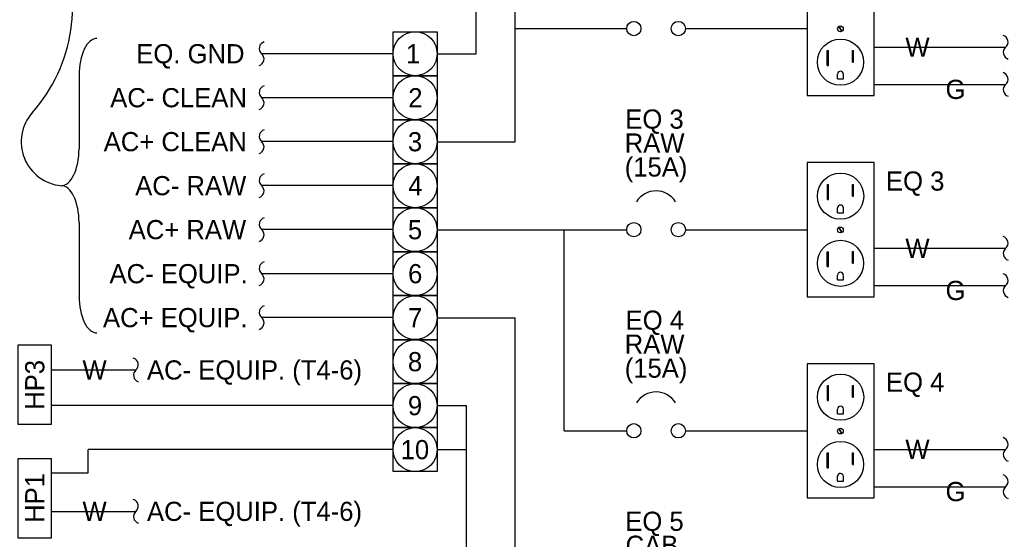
# Model space of a CAD drawing. Extents: x 99862 to 103680, y 99470 to 102076.
# Drawn here: x 100539 to 101158, y 100347 to 100673 of the extents above; entities that cross this region are included whole.
import ezdxf

# ---------------------------------------------------------------- set-up
doc = ezdxf.new("R2010")
doc.units = 0
for name, color, linetype in [('Level 11', 7, 'Continuous'), ('Level 15', 7, 'Continuous'), ('Level 20', 7, 'Continuous'), ('Level 26', 7, 'Continuous'), ('Level 3', 7, 'Continuous'), ('Level 40', 7, 'Continuous')]:
    doc.layers.add(name, color=color, linetype=linetype)

msp = doc.modelspace()

# ---------------------------------------------------------------- linework, layer by layer
at = {"layer": 'Level 11'}
for p, q in [((101044.66, 100643.9), (101044.66, 100653.27)), ((101044.66, 100653.27), (101045.4, 100653.27)), ((101045.4, 100643.9), (101045.4, 100653.27)), ((101060.34, 100646.01), (101060.34, 100653.33)), ((101060.34, 100653.33), (101061.06, 100653.33)), ((101061.06, 100646.01), (101061.06, 100653.33)), ((101060.34, 100646.01), (101061.06, 100646.01)), ((101044.66, 100643.9), (101045.4, 100643.9)), ((101051, 100635.57), (101051, 100638.61)), ((101051, 100635.57), (101054.72, 100635.57)), ((101054.72, 100635.57), (101054.72, 100638.48)), ((101044.77, 100560.05), (101044.77, 100569.44)), ((101044.77, 100569.44), (101045.47, 100569.44)), ((101045.47, 100560.05), (101045.47, 100569.44)), ((101060.41, 100562.18), (101060.41, 100569.46)), ((101060.41, 100569.46), (101061.15, 100569.46)), ((101061.15, 100562.18), (101061.15, 100569.46)), ((101044.77, 100560.05), (101045.47, 100560.05)), ((101060.41, 100562.18), (101061.15, 100562.18)), ((101051.09, 100551.71), (101051.09, 100554.74)), ((101054.82, 100551.71), (101054.82, 100554.76)), ((101051.09, 100551.71), (101054.82, 100551.71)), ((101060.34, 100520.1), (101060.34, 100527.42)), ((101060.34, 100527.42), (101061.06, 100527.42)), ((101061.06, 100520.1), (101061.06, 100527.42)), ((101044.66, 100518), (101044.66, 100527.36)), ((101044.66, 100527.36), (101045.4, 100527.36)), ((101045.4, 100518), (101045.4, 100527.36)), ((101044.66, 100518), (101045.4, 100518)), ((101060.34, 100520.1), (101061.06, 100520.1)), ((101051, 100509.66), (101051, 100512.7)), ((101051, 100509.66), (101054.72, 100509.66)), ((101054.72, 100509.66), (101054.72, 100512.57)), ((101044.77, 100434.14), (101044.77, 100443.53)), ((101044.77, 100443.53), (101045.47, 100443.53)), ((101045.47, 100434.14), (101045.47, 100443.53)), ((101060.41, 100436.27), (101060.41, 100443.55)), ((101060.41, 100443.55), (101061.15, 100443.55)), ((101061.15, 100436.27), (101061.15, 100443.55)), ((101060.41, 100436.27), (101061.15, 100436.27)), ((101044.77, 100434.14), (101045.47, 100434.14)), ((101051.09, 100425.8), (101051.09, 100428.83)), ((101054.82, 100425.8), (101054.82, 100428.85)), ((101051.09, 100425.8), (101054.82, 100425.8)), ((101044.66, 100392.09), (101044.66, 100401.45)), ((101044.66, 100401.45), (101045.4, 100401.45)), ((101045.4, 100392.09), (101045.4, 100401.45)), ((101060.34, 100394.19), (101060.34, 100401.51)), ((101060.34, 100401.51), (101061.06, 100401.51)), ((101061.06, 100394.19), (101061.06, 100401.51)), ((101044.66, 100392.09), (101045.4, 100392.09)), ((101060.34, 100394.19), (101061.06, 100394.19)), ((101051, 100383.75), (101051, 100386.79)), ((101054.72, 100383.75), (101054.72, 100386.66)), ((101051, 100383.75), (101054.72, 100383.75))]:
    msp.add_line(p, q, dxfattribs=at)
for centre in [(101052.88, 100646), (101052.98, 100562.16), (101052.88, 100520.09), (101052.98, 100436.25), (101052.88, 100394.18)]:
    msp.add_circle(centre, 14.45, dxfattribs=at)
for centre, start, end in [((101052.86, 100638.5), 359.7062, 176.45807), ((101052.97, 100554.73), 1.14913, 179.35263), ((101052.86, 100512.59), 359.7062, 176.45807), ((101052.97, 100428.82), 1.14913, 179.35263), ((101052.86, 100386.68), 359.7062, 176.45807)]:
    msp.add_arc(centre, 1.86, start, end, dxfattribs=at)
at = {"layer": 'Level 15'}
for p, q in [((100576.18, 100637.83), (100576.18, 100591.75)), ((100576.18, 100545.67), (100576.18, 100499.59))]:
    msp.add_line(p, q, dxfattribs=at)
for centre, radius, start, end in [((100471.24, 100681.15), 100.9, 318.54148, 90), ((100567.48, 100596.12), 27.52, 138.54148, 264.99411)]:
    msp.add_arc(centre, radius, start, end, dxfattribs=at)
for centre, major_axis, start_param, end_param in [((100587.29, 100637.83), (0, 23.04), 6.283174, 7.853982), ((100565.08, 100591.75), (0, -23.04), 6.283174, 7.853982), ((100565.08, 100545.67), (0, 23.04), 4.712389, 6.283196), ((100587.29, 100499.59), (0, -23.04), 4.712389, 6.283196)]:
    msp.add_ellipse(centre, major_axis=major_axis, ratio=0.481891, start_param=start_param, end_param=end_param, dxfattribs=at)
at = {"layer": 'Level 26'}
for p, q in [((100849.3, 100596.23), (100849.3, 100792.97)), ((100824.83, 100651.32), (100824.83, 100711.95)), ((100849.3, 100667.06), (100919.06, 100667.06)), ((100955.87, 100667.06), (101031.99, 100667.06)), ((100772.83, 100651.32), (100690.46, 100651.32)), ((100800.35, 100651.32), (100824.83, 100651.32)), ((101073.96, 100655.4), (101156.33, 100655.4)), ((101073.96, 100632.07), (101156.33, 100632.07)), ((100772.83, 100623.79), (100690.46, 100623.79)), ((100772.83, 100596.27), (100690.46, 100596.27)), ((100800.35, 100596.23), (100849.3, 100596.23)), ((100772.83, 100568.71), (100690.46, 100568.71)), ((100772.83, 100541.2), (100690.46, 100541.2)), ((100800.35, 100541.15), (100879.83, 100541.15)), ((100879.83, 100541.15), (100919.06, 100541.15)), ((100879.83, 100415.24), (100879.83, 100541.15)), ((100955.87, 100541.15), (101031.99, 100541.15)), ((101073.96, 100529.49), (101156.33, 100529.49)), ((100772.83, 100513.61), (100690.46, 100513.61)), ((101073.96, 100506.16), (101156.33, 100506.16)), ((100772.83, 100486.1), (100690.46, 100486.1)), ((100800.35, 100486.06), (100849.3, 100486.06)), ((100849.3, 100289.33), (100849.3, 100486.06)), ((100558.72, 100453.33), (100611.77, 100453.33)), ((100772.83, 100431.06), (100558.72, 100431.06)), ((100800.35, 100430.98), (100818.77, 100430.98)), ((100818.77, 100261.79), (100818.77, 100430.98)), ((100879.83, 100415.24), (100919.06, 100415.24)), ((100955.87, 100415.24), (101031.99, 100415.24)), ((100772.83, 100403.51), (100581.87, 100403.51)), ((100581.87, 100388.98), (100581.87, 100403.51)), ((100800.35, 100403.44), (100818.77, 100403.44)), ((101073.96, 100403.58), (101156.33, 100403.58)), ((100558.72, 100388.98), (100581.87, 100388.98)), ((101073.96, 100380.25), (101156.33, 100380.25)), ((100558.72, 100364.81), (100611.77, 100364.81))]:
    msp.add_line(p, q, dxfattribs=at)
for points in [[(100538.13, 100469.15), (100558.72, 100469.15), (100558.72, 100419.28), (100538.13, 100419.28)], [(100538.13, 100397.79), (100558.72, 100397.79), (100558.72, 100347.92), (100538.13, 100347.92)]]:
    msp.add_lwpolyline(points, close=True, dxfattribs=at)
for centre in [(100923.53, 100667.06), (100951.4, 100667.06), (100923.53, 100541.15), (100951.4, 100541.15), (100923.53, 100415.24), (100951.4, 100415.24)]:
    msp.add_circle(centre, 4.47, dxfattribs=at)
for centre, radius, start, end in [((100693.23, 100654.58), 4.28, 105.71675, 229.67869), ((101153.56, 100658.66), 4.28, 310.32131, 74.28325), ((100687.69, 100648.05), 4.28, 285.71675, 49.67869), ((101159.1, 100652.13), 4.28, 130.32131, 254.28325), ((101153.56, 100635.34), 4.28, 310.32131, 74.28325), ((100693.23, 100627.06), 4.28, 105.71675, 229.67869), ((101159.1, 100628.81), 4.28, 130.32131, 254.28325), ((100687.69, 100620.53), 4.28, 285.71675, 49.67869), ((100693.23, 100599.54), 4.28, 105.71675, 229.67869), ((100687.69, 100593), 4.28, 285.71675, 49.67869), ((100693.23, 100571.98), 4.28, 105.71675, 229.67869), ((100687.69, 100565.44), 4.28, 285.71675, 49.67869), ((100937.46, 100551.09), 14.35, 31.81592, 148.18408), ((100693.23, 100544.47), 4.28, 105.71675, 229.67869), ((100687.69, 100537.94), 4.28, 285.71675, 49.67869), ((101153.56, 100532.75), 4.28, 310.32131, 74.28325), ((101159.1, 100526.22), 4.28, 130.32131, 254.28325), ((100693.23, 100516.87), 4.28, 105.71675, 229.67869), ((100687.69, 100510.34), 4.28, 285.71675, 49.67869), ((101153.56, 100509.43), 4.28, 310.32131, 74.28325), ((101159.1, 100502.9), 4.28, 130.32131, 254.28325), ((100693.23, 100489.37), 4.28, 105.71675, 229.67869), ((100687.69, 100482.84), 4.28, 285.71675, 49.67869), ((100608.99, 100456.59), 4.28, 310.32131, 74.28325), ((100614.54, 100450.06), 4.28, 130.32131, 254.28325), ((100937.46, 100425.18), 14.35, 31.81592, 148.18408), ((101153.56, 100406.84), 4.28, 310.32131, 74.28325), ((101159.1, 100400.31), 4.28, 130.32131, 254.28325), ((101153.56, 100383.52), 4.28, 310.32131, 74.28325), ((101159.1, 100376.99), 4.28, 130.32131, 254.28325), ((100608.99, 100368.07), 4.28, 310.32131, 74.28325), ((100614.54, 100361.54), 4.28, 130.32131, 254.28325)]:
    msp.add_arc(centre, radius, start, end, dxfattribs=at)
at = {"layer": 'Level 3'}
for points in [[(100772.83, 100665.09), (100800.35, 100665.09), (100800.35, 100637.55), (100772.83, 100637.55)], [(100772.83, 100637.55), (100800.35, 100637.55), (100800.35, 100610), (100772.83, 100610)], [(100772.83, 100610), (100800.35, 100610), (100800.35, 100582.46), (100772.83, 100582.46)], [(100772.83, 100582.46), (100800.35, 100582.46), (100800.35, 100554.92), (100772.83, 100554.92)], [(100772.83, 100554.92), (100800.35, 100554.92), (100800.35, 100527.38), (100772.83, 100527.38)], [(100772.83, 100527.38), (100800.35, 100527.38), (100800.35, 100499.84), (100772.83, 100499.84)], [(100772.83, 100499.84), (100800.35, 100499.84), (100800.35, 100472.29), (100772.83, 100472.29)], [(100772.83, 100472.29), (100800.35, 100472.29), (100800.35, 100444.75), (100772.83, 100444.75)], [(100772.83, 100444.75), (100800.35, 100444.75), (100800.35, 100417.21), (100772.83, 100417.21)], [(100772.83, 100417.21), (100800.35, 100417.21), (100800.35, 100389.67), (100772.83, 100389.67)]]:
    msp.add_lwpolyline(points, close=True, dxfattribs=at)
for centre in [(100786.59, 100651.32), (100786.59, 100623.77), (100786.59, 100596.23), (100786.59, 100568.69), (100786.59, 100541.15), (100786.59, 100513.61), (100786.59, 100486.06), (100786.59, 100458.52), (100786.59, 100430.98), (100786.59, 100403.44)]:
    msp.add_circle(centre, 13.76, dxfattribs=at)
at = {"layer": 'Level 40'}
for p, q in [((101053.62, 100665.62), (101052.15, 100668.16)), ((101053.82, 100665.65), (101052.29, 100668.32)), ((101053.62, 100539.71), (101052.15, 100542.25)), ((101053.82, 100539.74), (101052.29, 100542.41)), ((101053.62, 100413.8), (101052.15, 100416.34)), ((101053.82, 100413.83), (101052.29, 100416.5))]:
    msp.add_line(p, q, dxfattribs=at)
for points in [[(101031.99, 100709.02), (101031.99, 100625.1), (101073.96, 100625.1), (101073.96, 100709.02)], [(101031.99, 100583.11), (101031.99, 100499.19), (101073.96, 100499.19), (101073.96, 100583.11)], [(101031.99, 100457.2), (101031.99, 100373.28), (101073.96, 100373.28), (101073.96, 100457.2)]]:
    msp.add_lwpolyline(points, close=True, dxfattribs=at)
for centre in [(101052.88, 100666.89), (101052.88, 100540.98), (101052.88, 100415.07)]:
    msp.add_circle(centre, 1.81, dxfattribs=at)

# ---------------------------------------------------------------- texts
at = {"layer": 'Level 20'}
for s, height, p in [('EQ. GND', 12, (100612.01, 100645.32)), ('W', 12.01, (101093.55, 100649.39)), ('1', 12, (100780.82, 100645.32)), ('G', 12.01, (101118.7, 100623)), ('AC- CLEAN', 12, (100595.69, 100617.79)), ('2', 12, (100782.29, 100617.77)), ('EQ 3', 12, (100918.16, 100604.4)), ('AC+ CLEAN', 12, (100591.6, 100590.27)), ('3', 12, (100782.06, 100590.23)), ('RAW', 12, (100917.82, 100589.4)), ('(15A)', 12, (100917.82, 100574.4)), ('EQ 3', 12, (101081.4, 100565.61)), ('AC- RAW', 12, (100611.33, 100562.71)), ('4', 12, (100782.29, 100562.69)), ('AC+ RAW', 12, (100607.23, 100535.2)), ('5', 12, (100782.06, 100535.15)), ('W', 12.01, (101093.55, 100523.48)), ('AC- EQUIP.', 12, (100595.25, 100507.61)), ('6', 12, (100782.18, 100507.61)), ('G', 12.01, (101118.7, 100497.1)), ('AC+ EQUIP.', 12, (100591.16, 100480.1)), ('7', 12, (100782.18, 100480.06)), ('EQ 4', 12, (100918.39, 100478.49)), ('RAW', 12, (100917.82, 100463.49)), ('W', 12.01, (100578.31, 100447.33)), ('AC- EQUIP. (T4-6)', 12, (100618.71, 100447.33)), ('8', 12, (100782.06, 100452.52)), ('(15A)', 12, (100917.82, 100448.49)), ('EQ 4', 12, (101081.4, 100439.7)), ('9', 12, (100782.06, 100424.98)), ('10', 12, (100777.53, 100397.44)), ('W', 12.01, (101093.55, 100397.57)), ('G', 12.01, (101118.7, 100371.19)), ('W', 12.01, (100578.31, 100358.81)), ('AC- EQUIP. (T4-6)', 12, (100618.71, 100358.81)), ('EQ 5', 12, (100918.16, 100352.58)), ('CAB.', 12, (100918.39, 100337.58))]:
    msp.add_text(s, height=height, dxfattribs=at).set_placement(p)
for s, p in [('HP3', (100554.42, 100428.37)), ('HP1', (100554.42, 100357.58))]:
    msp.add_text(s, height=12, rotation=90, dxfattribs=at).set_placement(p)

doc.saveas('drawing.dxf')
